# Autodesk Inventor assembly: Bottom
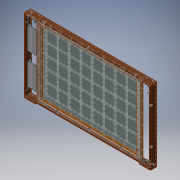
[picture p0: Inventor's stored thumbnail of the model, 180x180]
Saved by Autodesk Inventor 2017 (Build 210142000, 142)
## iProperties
Created: 2017-05
Part Number: Bottom
Document SubType Name: Assembly
Designer: Savy
Author: Savy
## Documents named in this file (20)
- D:\3D Printer Designs\John Ledden Designs\Infinity Mirror Table\SavanDrawings\Bottom.iam
- D:\3D Printer Designs\John Ledden Designs\Infinity Mirror Table\SavanDrawings\BottomInnerPanel_Long.ipt
- D:\3D Printer Designs\John Ledden Designs\Infinity Mirror Table\SavanDrawings\BottomInnerPanel_Short.ipt
- D:\3D Printer Designs\John Ledden Designs\Infinity Mirror Table\SavanDrawings\Mirror.ipt
- D:\3D Printer Designs\John Ledden Designs\Infinity Mirror Table\SavanDrawings\BottomInnerSpacer_Long.ipt
- D:\3D Printer Designs\John Ledden Designs\Infinity Mirror Table\SavanDrawings\BottomInnerSpacer_Short.ipt
- D:\3D Printer Designs\John Ledden Designs\Infinity Mirror Table\SavanDrawings\BottomBase_Short.ipt
- D:\3D Printer Designs\John Ledden Designs\Infinity Mirror Table\SavanDrawings\BottomSide_Long1.ipt
- D:\3D Printer Designs\John Ledden Designs\Infinity Mirror Table\SavanDrawings\BottomSide_Long2.ipt
- D:\3D Printer Designs\John Ledden Designs\Infinity Mirror Table\SavanDrawings\PSU_AC.ipt
- D:\3D Printer Designs\John Ledden Designs\Infinity Mirror Table\SavanDrawings\USBPorts.ipt
- D:\3D Printer Designs\John Ledden Designs\Infinity Mirror Table\SavanDrawings\ChannelAssembly.iam
- D:\3D Printer Designs\John Ledden Designs\Infinity Mirror Table\SavanDrawings\USBMount.ipt
- D:\3D Printer Designs\John Ledden Designs\Infinity Mirror Table\SavanDrawings\8_Screw_1inch.ipt
- D:\3D Printer Designs\John Ledden Designs\Infinity Mirror Table\SavanDrawings\8_Screw_1-25inch.ipt
- D:\3D Printer Designs\John Ledden Designs\Infinity Mirror Table\SavanDrawings\8_Screw_-5inch.ipt
- D:\3D Printer Designs\John Ledden Designs\Infinity Mirror Table\SavanDrawings\BottomSide_Short.ipt
- D:\3D Printer Designs\John Ledden Designs\Infinity Mirror Table\SavanDrawings\90DegBracket.ipt
- D:\3D Printer Designs\John Ledden Designs\Infinity Mirror Table\SavanDrawings\LBracket.ipt
- D:\3D Printer Designs\John Ledden Designs\Infinity Mirror Table\SavanDrawings\Magnet.ipt
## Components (140 placed, 108 different names)
1. BottomInnerPanel_Long_1177
2. BottomInnerPanel_Short_1178
3. BottomInnerPanel_Long_1179
4. BottomInnerPanel_Short_1180
5. Mirror_1181
6. BottomInnerSpacer_Long_1182
7. BottomInnerSpacer_Short_1183
8. BottomInnerSpacer_Long_1184
9. BottomInnerSpacer_Short_1185
10. BottomBase_Short_1186 — Insert:7, Insert:8, Insert:9, Insert:10, Insert:11, Insert:12
11. BottomBase_Short_1187 — Insert:1, Insert:2, Insert:3, Insert:4, Insert:5, Insert:6
12. BottomSide_Long1_1188 — Flush:1, Mate:1, Mate:2, Mate:3, Mate:5
13. BottomSide_Long1_1189 — Mate:19, Mate:20, Mate:21, Mate:22, Mate:23
14. BottomSide_Long1_1190 — Mate:13, Mate:14, Mate:15, Mate:16
15. BottomSide_Long1_1191 — Mate:7, Mate:8, Mate:9, Mate:10
16. BottomSide_Long2_1192
17. BottomSide_Long2_1193
18. PSU_AC_1194
19. PSU_AC_1195
20. USBPorts_1196
21. USBPorts_1197
22. ChannelAssembly_1198 [sub-assembly]
23. USBMount_1199
24. USBMount_1200
25. 8_Screw_1inch_1201
26. 8_Screw_1inch_1202
27. 8_Screw_1inch_1203
28. 8_Screw_1inch_1204
29. 8_Screw_1inch_1205 — Insert:2
30. 8_Screw_1inch_1206 — Insert:1
31. 8_Screw_1-25inch_1207
32. 8_Screw_1-25inch_1208
33. 8_Screw_1-25inch_1209
34. 8_Screw_1-25inch_1210
35. 8_Screw_1-25inch_1211
36. 8_Screw_1-25inch_1212
37. 8_Screw_1-25inch_1213
38. 8_Screw_1-25inch_1214
39. 8_Screw_1-25inch_1215
40. 8_Screw_1-25inch_1216
41. 8_Screw_1-25inch_1217
42. 8_Screw_1-25inch_1218
43. 8_Screw_1-25inch_1219
44. 8_Screw_1-25inch_1220
45. 8_Screw_1-25inch_1221
46. 8_Screw_1-25inch_1222
47. 8_Screw_1-25inch_1223
48. 8_Screw_1-25inch_1224
49. 8_Screw_1-25inch_1225
50. 8_Screw_1-25inch_1226
51. 8_Screw_1inch_1227
52. 8_Screw_1inch_1228
53. 8_Screw_1inch_1229
54. 8_Screw_1inch_1230
55. 8_Screw_-5inch_1231
56. 8_Screw_-5inch_1232
57. 8_Screw_-5inch_1233
58. 8_Screw_-5inch_1234
59. 8_Screw_-5inch_1235
60. 8_Screw_-5inch_1236
61. 8_Screw_-5inch_1237
62. 8_Screw_-5inch_1238
63. BottomSide_Short_1247
64. BottomSide_Short_1248
65. 90DegBracket_1249
66. 90DegBracket_1250
67. 90DegBracket_1251
68. 90DegBracket_1252
69. 90DegBracket_1253
70. 90DegBracket_1254
71. 90DegBracket_1255
72. 90DegBracket_1256
73. 90DegBracket_1257
74. 90DegBracket_1258
75. 8_Screw_-5inch_1259
76. 8_Screw_-5inch_1260
77. 8_Screw_-5inch_1261
78. 8_Screw_-5inch_1262
79. 8_Screw_-5inch_1263
80. 8_Screw_-5inch_1264
81. 8_Screw_-5inch_1265
82. 8_Screw_-5inch_1266
83. 8_Screw_-5inch_1267
84. 8_Screw_-5inch_1268
85. 8_Screw_-5inch_1269
86. 8_Screw_-5inch_1270
87. 8_Screw_-5inch_1271
88. 8_Screw_-5inch_1272
89. 8_Screw_-5inch_1273
90. 8_Screw_-5inch_1274
91. 8_Screw_-5inch_1275
92. 8_Screw_-5inch_1276
93. 8_Screw_-5inch_1277
94. 8_Screw_-5inch_1278
95. LBracket_1279
96. LBracket_1280
97. LBracket_1281
98. LBracket_1282
99. 8_Screw_-5inch_1283
100. 8_Screw_-5inch_1284
101. 8_Screw_-5inch_1285
102. 8_Screw_-5inch_1286
103. 8_Screw_-5inch_1287
104. 8_Screw_-5inch_1288
105. 8_Screw_-5inch_1289
106. 8_Screw_-5inch_1290
107. Magnet:1 — Flush:1
108. Magnet:2 — Mate:1
109. Magnet:3 — Mate:4
110. Magnet:7 — Mate:3, Mate:4
111. Magnet:8 — Mate:5
112. Magnet:9 — Mate:2
113. Magnet:10 — Mate:8
114. Magnet:11 — Mate:7
115. Magnet:12
116. Magnet:13 — Mate:9
117. Magnet:14 — Mate:11
118. Magnet:15 — Mate:10, Mate:11
119. Magnet:16 — Mate:14
120. Magnet:17 — Mate:13
121. Magnet:18
122. Magnet:19 — Mate:15
123. Magnet:20 — Mate:17
124. Magnet:21 — Mate:16, Mate:17
125. Magnet:22 — Mate:20
126. Magnet:23 — Mate:19
127. Magnet:24
128. Magnet:25 — Mate:21
129. Magnet:26 — Mate:23
130. Magnet:27 — Mate:22
131. 8_Screw_1inch:11 — Insert:3
132. 8_Screw_1inch:12 — Insert:4
133. 8_Screw_1inch:13 — Insert:5
134. 8_Screw_1inch:14 — Insert:6
135. 8_Screw_1inch:15 — Insert:7
136. 8_Screw_1inch:16 — Insert:8
137. 8_Screw_1inch:17 — Insert:9
138. 8_Screw_1inch:18 — Insert:10
139. 8_Screw_1inch:19 — Insert:11
140. 8_Screw_1inch:20 — Insert:12
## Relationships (33: Mate 20, Insert 12, Flush 1)
- Flush:1: BottomSide_Long1_1188 ↔ Magnet:1
- Mate:1: BottomSide_Long1_1188 ↔ Magnet:2
- Mate:2: BottomSide_Long1_1188 ↔ Magnet:9
- Mate:3: BottomSide_Long1_1188 ↔ Magnet:7
- Mate:4: Magnet:3 ↔ Magnet:7
- Mate:5: BottomSide_Long1_1188 ↔ Magnet:8
- Mate:7: BottomSide_Long1_1191 ↔ Magnet:11
- Mate:8: BottomSide_Long1_1191 ↔ Magnet:10
- Mate:9: BottomSide_Long1_1191 ↔ Magnet:13
- Mate:10: BottomSide_Long1_1191 ↔ Magnet:15
- Mate:11: Magnet:14 ↔ Magnet:15
- Mate:13: BottomSide_Long1_1190 ↔ Magnet:17
- Mate:14: BottomSide_Long1_1190 ↔ Magnet:16
- Mate:15: BottomSide_Long1_1190 ↔ Magnet:19
- Mate:16: BottomSide_Long1_1190 ↔ Magnet:21
- Mate:17: Magnet:20 ↔ Magnet:21
- Mate:19: BottomSide_Long1_1189 ↔ Magnet:23
- Mate:20: BottomSide_Long1_1189 ↔ Magnet:22
- Mate:21: BottomSide_Long1_1189 ↔ Magnet:25
- Mate:22: BottomSide_Long1_1189 ↔ Magnet:27
- Mate:23: BottomSide_Long1_1189 ↔ Magnet:26
- Insert:1: BottomBase_Short_1187 ↔ 8_Screw_1inch_1206
- Insert:2: BottomBase_Short_1187 ↔ 8_Screw_1inch_1205
- Insert:3: BottomBase_Short_1187 ↔ 8_Screw_1inch:11
- Insert:4: BottomBase_Short_1187 ↔ 8_Screw_1inch:12
- Insert:5: BottomBase_Short_1187 ↔ 8_Screw_1inch:13
- Insert:6: BottomBase_Short_1187 ↔ 8_Screw_1inch:14
- Insert:7: BottomBase_Short_1186 ↔ 8_Screw_1inch:15
- Insert:8: BottomBase_Short_1186 ↔ 8_Screw_1inch:16
- Insert:9: BottomBase_Short_1186 ↔ 8_Screw_1inch:17
- Insert:10: BottomBase_Short_1186 ↔ 8_Screw_1inch:18
- Insert:11: BottomBase_Short_1186 ↔ 8_Screw_1inch:19
- Insert:12: BottomBase_Short_1186 ↔ 8_Screw_1inch:20
## Named parameters: d6_d4 = 0, d12_d4 = 0, d18_d4 = 0
